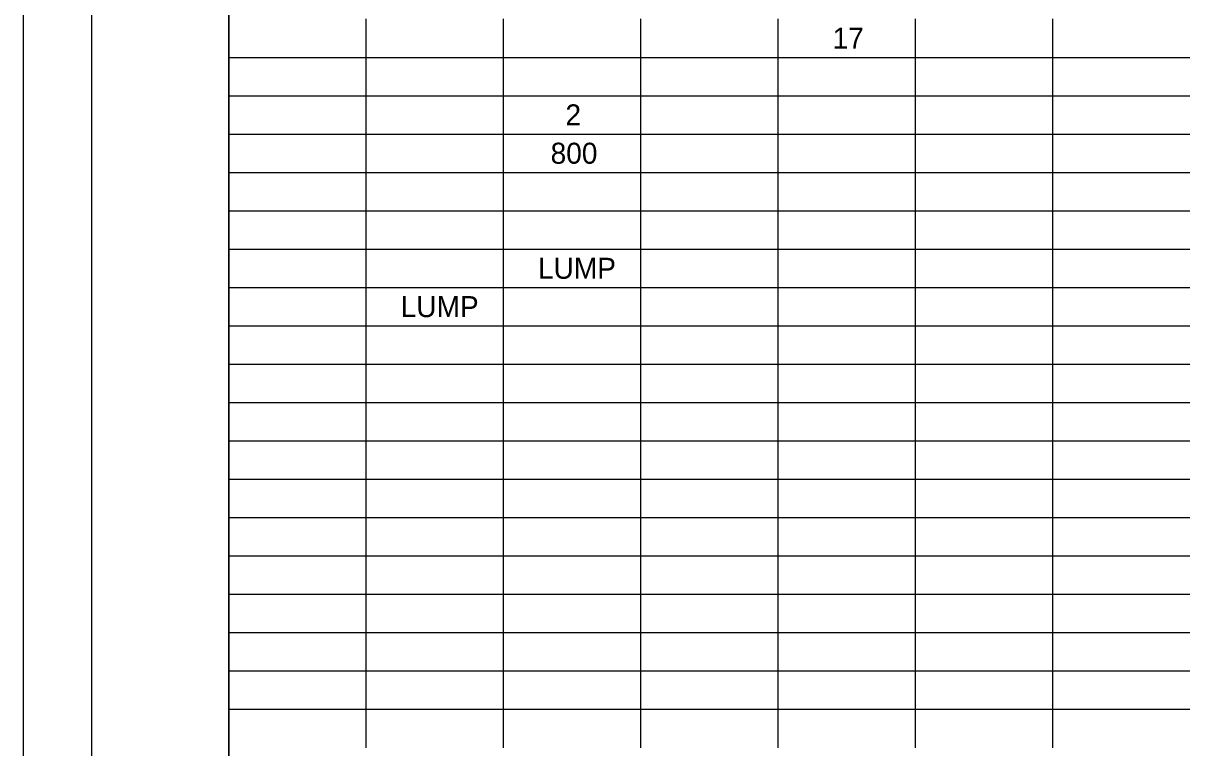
# Model space of a CAD drawing. Extents: x 0 to 34, y 0 to 22.
# Drawn here: x 0 to 8.52, y 11.42 to 16.71 of the extents above; entities that cross this region are included whole.
import ezdxf

# ---------------------------------------------------------------- set-up
doc = ezdxf.new("R2010")
doc.units = 0
for name, color, linetype in [('SH_Border', 7, 'Continuous'), ('SH_Cut_Line', 7, 'Continuous'), ('SH_Text', 7, 'Continuous')]:
    doc.layers.add(name, color=color, linetype=linetype)

msp = doc.modelspace()

# ---------------------------------------------------------------- linework, layer by layer
at = {"layer": 'SH_Border'}
for points in [[(0.5, 21.5), (1.5, 21.5), (1.5, 0.5), (0.5, 0.5)], [(1.5, 21.5), (33.5, 21.5), (33.5, 0.5), (1.5, 0.5)]]:
    msp.add_lwpolyline(points, close=True, dxfattribs=at)
at = {"layer": 'SH_Cut_Line'}
msp.add_lwpolyline([(0, 0), (34, 0), (34, 22), (0, 22)], close=True, dxfattribs=at)
at = {"layer": 'SH_Text'}
for p, q in [((1.5, 16.74), (1.5, 16.18)), ((2.5025, 16.74), (2.5025, 16.18)), ((3.5051, 16.74), (3.5051, 16.18)), ((4.5076, 16.74), (4.5076, 16.18)), ((5.5101, 16.74), (5.5101, 16.18)), ((6.5126, 16.74), (6.5126, 16.18)), ((7.5152, 16.74), (7.5152, 16.18)), ((1.5, 16.46), (2.5025, 16.46)), ((2.5025, 16.46), (3.5051, 16.46)), ((3.5051, 16.46), (4.5076, 16.46)), ((4.5076, 16.46), (5.5101, 16.46)), ((5.5101, 16.46), (6.5126, 16.46)), ((6.5126, 16.46), (7.5152, 16.46)), ((7.5152, 16.46), (8.5177, 16.46)), ((1.5, 16.18), (2.5025, 16.18)), ((1.5, 16.18), (1.5, 15.9)), ((2.5025, 16.18), (3.5051, 16.18)), ((2.5025, 16.18), (2.5025, 15.9)), ((3.5051, 16.18), (4.5076, 16.18)), ((3.5051, 16.18), (3.5051, 15.9)), ((4.5076, 16.18), (5.5101, 16.18)), ((4.5076, 16.18), (4.5076, 15.9)), ((5.5101, 16.18), (6.5126, 16.18)), ((5.5101, 16.18), (5.5101, 15.9)), ((6.5126, 16.18), (7.5152, 16.18)), ((6.5126, 16.18), (6.5126, 15.9)), ((7.5152, 16.18), (8.5177, 16.18)), ((7.5152, 16.18), (7.5152, 15.9)), ((1.5, 15.9), (2.5025, 15.9)), ((1.5, 15.9), (1.5, 15.62)), ((2.5025, 15.9), (3.5051, 15.9)), ((2.5025, 15.9), (2.5025, 15.62)), ((3.5051, 15.9), (4.5076, 15.9)), ((3.5051, 15.9), (3.5051, 15.62)), ((4.5076, 15.9), (5.5101, 15.9)), ((4.5076, 15.9), (4.5076, 15.62)), ((5.5101, 15.9), (6.5126, 15.9)), ((5.5101, 15.9), (5.5101, 15.62)), ((6.5126, 15.9), (7.5152, 15.9)), ((6.5126, 15.9), (6.5126, 15.62)), ((7.5152, 15.9), (8.5177, 15.9)), ((7.5152, 15.9), (7.5152, 15.62)), ((1.5, 15.62), (2.5025, 15.62)), ((1.5, 15.62), (1.5, 15.34)), ((2.5025, 15.62), (3.5051, 15.62)), ((2.5025, 15.62), (2.5025, 15.34)), ((3.5051, 15.62), (4.5076, 15.62)), ((3.5051, 15.62), (3.5051, 15.34)), ((4.5076, 15.62), (5.5101, 15.62)), ((4.5076, 15.62), (4.5076, 15.34)), ((5.5101, 15.62), (6.5126, 15.62)), ((5.5101, 15.62), (5.5101, 15.34)), ((6.5126, 15.62), (7.5152, 15.62)), ((6.5126, 15.62), (6.5126, 15.34)), ((7.5152, 15.62), (8.5177, 15.62)), ((7.5152, 15.62), (7.5152, 15.34)), ((1.5, 15.34), (2.5025, 15.34)), ((1.5, 15.34), (1.5, 14.78)), ((2.5025, 15.34), (3.5051, 15.34)), ((2.5025, 15.34), (2.5025, 14.78)), ((3.5051, 15.34), (4.5076, 15.34)), ((3.5051, 15.34), (3.5051, 14.78)), ((4.5076, 15.34), (5.5101, 15.34)), ((4.5076, 15.34), (4.5076, 14.78)), ((5.5101, 15.34), (6.5126, 15.34)), ((5.5101, 15.34), (5.5101, 14.78)), ((6.5126, 15.34), (7.5152, 15.34)), ((6.5126, 15.34), (6.5126, 14.78)), ((7.5152, 15.34), (8.5177, 15.34)), ((7.5152, 15.34), (7.5152, 14.78)), ((1.5, 15.06), (2.5025, 15.06)), ((2.5025, 15.06), (3.5051, 15.06)), ((3.5051, 15.06), (4.5076, 15.06)), ((4.5076, 15.06), (5.5101, 15.06)), ((5.5101, 15.06), (6.5126, 15.06)), ((6.5126, 15.06), (7.5152, 15.06)), ((7.5152, 15.06), (8.5177, 15.06)), ((1.5, 14.78), (2.5025, 14.78)), ((1.5, 14.78), (1.5, 14.5)), ((2.5025, 14.78), (3.5051, 14.78)), ((2.5025, 14.78), (2.5025, 14.5)), ((3.5051, 14.78), (4.5076, 14.78)), ((3.5051, 14.78), (3.5051, 14.5)), ((4.5076, 14.78), (5.5101, 14.78)), ((4.5076, 14.78), (4.5076, 14.5)), ((5.5101, 14.78), (6.5126, 14.78)), ((5.5101, 14.78), (5.5101, 14.5)), ((6.5126, 14.78), (7.5152, 14.78)), ((6.5126, 14.78), (6.5126, 14.5)), ((7.5152, 14.78), (8.5177, 14.78)), ((7.5152, 14.78), (7.5152, 14.5)), ((1.5, 14.5), (2.5025, 14.5)), ((1.5, 14.5), (1.5, 14.22)), ((2.5025, 14.5), (3.5051, 14.5)), ((2.5025, 14.5), (2.5025, 14.22)), ((3.5051, 14.5), (4.5076, 14.5)), ((3.5051, 14.5), (3.5051, 14.22)), ((4.5076, 14.5), (5.5101, 14.5)), ((4.5076, 14.5), (4.5076, 14.22)), ((5.5101, 14.5), (6.5126, 14.5)), ((5.5101, 14.5), (5.5101, 14.22)), ((6.5126, 14.5), (7.5152, 14.5)), ((6.5126, 14.5), (6.5126, 14.22)), ((7.5152, 14.5), (8.5177, 14.5)), ((7.5152, 14.5), (7.5152, 14.22)), ((1.5, 14.22), (2.5025, 14.22)), ((1.5, 14.22), (1.5, 13.94)), ((2.5025, 14.22), (3.5051, 14.22)), ((2.5025, 14.22), (2.5025, 13.94)), ((3.5051, 14.22), (4.5076, 14.22)), ((3.5051, 14.22), (3.5051, 13.94)), ((4.5076, 14.22), (5.5101, 14.22)), ((4.5076, 14.22), (4.5076, 13.94)), ((5.5101, 14.22), (6.5126, 14.22)), ((5.5101, 14.22), (5.5101, 13.94)), ((6.5126, 14.22), (7.5152, 14.22)), ((6.5126, 14.22), (6.5126, 13.94)), ((7.5152, 14.22), (8.5177, 14.22)), ((7.5152, 14.22), (7.5152, 13.94)), ((1.5, 13.94), (2.5025, 13.94)), ((1.5, 13.94), (1.5, 11.7)), ((2.5025, 13.94), (3.5051, 13.94)), ((2.5025, 13.94), (2.5025, 11.7)), ((3.5051, 13.94), (4.5076, 13.94)), ((3.5051, 13.94), (3.5051, 11.7)), ((4.5076, 13.94), (5.5101, 13.94)), ((4.5076, 13.94), (4.5076, 11.7)), ((5.5101, 13.94), (6.5126, 13.94)), ((5.5101, 13.94), (5.5101, 11.7)), ((6.5126, 13.94), (7.5152, 13.94)), ((6.5126, 13.94), (6.5126, 11.7)), ((7.5152, 13.94), (8.5177, 13.94)), ((7.5152, 13.94), (7.5152, 11.7)), ((1.5, 13.66), (2.5025, 13.66)), ((2.5025, 13.66), (3.5051, 13.66)), ((3.5051, 13.66), (4.5076, 13.66)), ((4.5076, 13.66), (5.5101, 13.66)), ((5.5101, 13.66), (6.5126, 13.66)), ((6.5126, 13.66), (7.5152, 13.66)), ((7.5152, 13.66), (8.5177, 13.66)), ((1.5, 13.38), (2.5025, 13.38)), ((2.5025, 13.38), (3.5051, 13.38)), ((3.5051, 13.38), (4.5076, 13.38)), ((4.5076, 13.38), (5.5101, 13.38)), ((5.5101, 13.38), (6.5126, 13.38)), ((6.5126, 13.38), (7.5152, 13.38)), ((7.5152, 13.38), (8.5177, 13.38)), ((1.5, 13.1), (2.5025, 13.1)), ((2.5025, 13.1), (3.5051, 13.1)), ((3.5051, 13.1), (4.5076, 13.1)), ((4.5076, 13.1), (5.5101, 13.1)), ((5.5101, 13.1), (6.5126, 13.1)), ((6.5126, 13.1), (7.5152, 13.1)), ((7.5152, 13.1), (8.5177, 13.1)), ((1.5, 12.82), (2.5025, 12.82)), ((2.5025, 12.82), (3.5051, 12.82)), ((3.5051, 12.82), (4.5076, 12.82)), ((4.5076, 12.82), (5.5101, 12.82)), ((5.5101, 12.82), (6.5126, 12.82)), ((6.5126, 12.82), (7.5152, 12.82)), ((7.5152, 12.82), (8.5177, 12.82)), ((1.5, 12.54), (2.5025, 12.54)), ((2.5025, 12.54), (3.5051, 12.54)), ((3.5051, 12.54), (4.5076, 12.54)), ((4.5076, 12.54), (5.5101, 12.54)), ((5.5101, 12.54), (6.5126, 12.54)), ((6.5126, 12.54), (7.5152, 12.54)), ((7.5152, 12.54), (8.5177, 12.54)), ((1.5, 12.26), (2.5025, 12.26)), ((2.5025, 12.26), (3.5051, 12.26)), ((3.5051, 12.26), (4.5076, 12.26)), ((4.5076, 12.26), (5.5101, 12.26)), ((5.5101, 12.26), (6.5126, 12.26)), ((6.5126, 12.26), (7.5152, 12.26)), ((7.5152, 12.26), (8.5177, 12.26)), ((1.5, 11.98), (2.5025, 11.98)), ((2.5025, 11.98), (3.5051, 11.98)), ((3.5051, 11.98), (4.5076, 11.98)), ((4.5076, 11.98), (5.5101, 11.98)), ((5.5101, 11.98), (6.5126, 11.98)), ((6.5126, 11.98), (7.5152, 11.98)), ((7.5152, 11.98), (8.5177, 11.98)), ((1.5, 11.7), (2.5025, 11.7)), ((1.5, 11.7), (1.5, 11.42)), ((2.5025, 11.7), (3.5051, 11.7)), ((2.5025, 11.7), (2.5025, 11.42)), ((3.5051, 11.7), (4.5076, 11.7)), ((3.5051, 11.7), (3.5051, 11.42)), ((4.5076, 11.7), (5.5101, 11.7)), ((4.5076, 11.7), (4.5076, 11.42)), ((5.5101, 11.7), (6.5126, 11.7)), ((5.5101, 11.7), (5.5101, 11.42)), ((6.5126, 11.7), (7.5152, 11.7)), ((6.5126, 11.7), (6.5126, 11.42)), ((7.5152, 11.7), (8.5177, 11.7)), ((7.5152, 11.7), (7.5152, 11.42))]:
    msp.add_line(p, q, dxfattribs=at)

# ---------------------------------------------------------------- texts
for s, height, p in [('17', 0.15333, (5.91, 16.5233)), ('2', 0.1533, (3.959, 15.9633)), ('800', 0.15333, (3.8507, 15.6833)), ('LUMP', 0.15333, (3.7582, 14.8433)), ('LUMP', 0.15333, (2.7557, 14.5633))]:
    msp.add_text(s, height=height, dxfattribs=at).set_placement(p)

doc.saveas('drawing.dxf')
